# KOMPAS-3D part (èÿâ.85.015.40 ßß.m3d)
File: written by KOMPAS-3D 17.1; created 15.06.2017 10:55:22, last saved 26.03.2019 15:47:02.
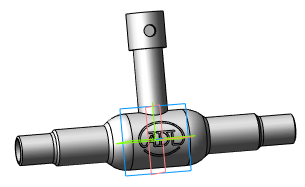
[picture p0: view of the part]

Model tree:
1. Операция без истории:2  (labels: Сталь 20  ГОСТ 1050-88)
